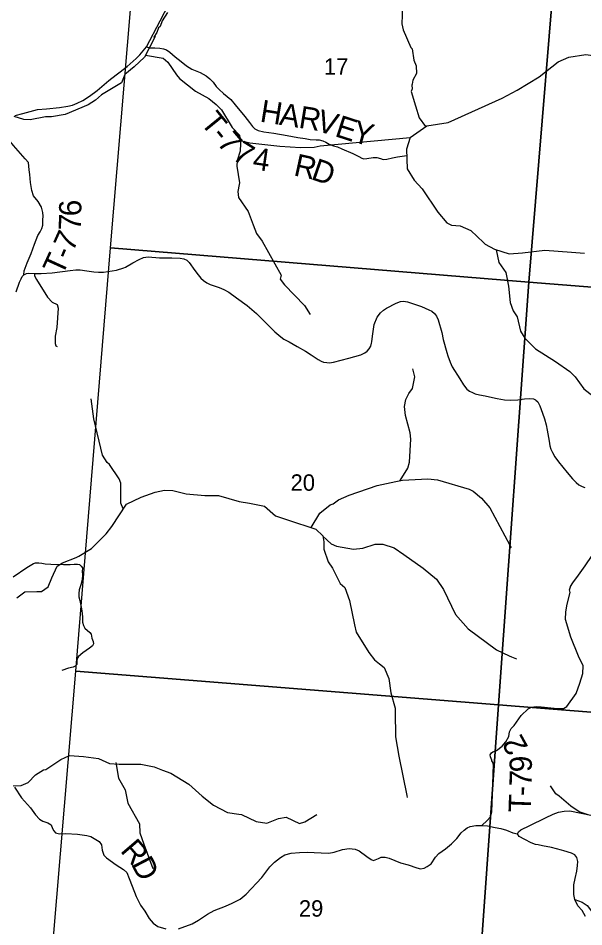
# Model space of a CAD drawing. Extents: x 1878108 to 2183446, y 146837 to 508383.
# Drawn here: x 1982625 to 1990241, y 255922 to 268162 of the extents above; entities that cross this region are included whole.
import ezdxf

# ---------------------------------------------------------------- set-up
doc = ezdxf.new("R2010")
doc.units = 0
for name, color, linetype in [('GM_X_County_Road', 7, 'Continuous'), ('GM_X_Minor_River', 7, 'Continuous'), ('GM_X_Section', 7, 'Continuous'), ('GM_X_Section_Text', 7, 'Continuous'), ('GM_X_State_Route', 7, 'Continuous'), ('GM_X_Township_Road', 7, 'Continuous'), ('GM_X_Township_Road_Text', 7, 'Continuous'), ('GM_X_Township_ROW', 7, 'Continuous')]:
    doc.layers.add(name, color=color, linetype=linetype)

msp = doc.modelspace()

# ---------------------------------------------------------------- linework, layer by layer
at = {"layer": 'GM_X_County_Road'}
for points in [[(1984047, 264799), (1984072, 264807), (1984168, 264867), (1984254, 264912), (1984314, 264940), (1984375, 264946), (1984526, 264934), (1984696, 264933), (1984805, 264931), (1984856, 264920), (1984894, 264901), (1984926, 264873), (1985005, 264761), (1985047, 264703), (1985085, 264660), (1985120, 264628), (1985165, 264599), (1985209, 264575), (1985331, 264536), (1985395, 264509), (1985462, 264469), (1985566, 264394), (1985707, 264291), (1985832, 264185), (1985976, 264039), (1986082, 263935), (1986160, 263871), (1986203, 263838), (1986272, 263802), (1986382, 263741), (1986494, 263676), (1986572, 263628), (1986664, 263565), (1986703, 263543), (1986737, 263530), (1986780, 263522), (1986819, 263521), (1986872, 263527), (1987076, 263580), (1987241, 263627), (1987294, 263653), (1987324, 263678), (1987351, 263707), (1987375, 263745), (1987383, 263782)], [(1982599, 264474), (1982644, 264606), (1982664, 264653), (1982681, 264681), (1982702, 264703), (1982736, 264721), (1982768, 264728), (1982846, 264723), (1982936, 264724), (1983085, 264733), (1983326, 264764), (1983401, 264772), (1983462, 264770), (1983549, 264757), (1983642, 264743), (1983706, 264739), (1983773, 264741), (1983947, 264767), (1984047, 264799)], [(1987383, 263782), (1987388, 263801), (1987397, 263877), (1987418, 264035), (1987460, 264133), (1987506, 264191), (1987545, 264227), (1987585, 264255), (1987716, 264324), (1987775, 264345), (1987815, 264349), (1987867, 264341), (1987950, 264316), (1988055, 264276), (1988156, 264231), (1988194, 264213), (1988230, 264182), (1988259, 264146), (1988281, 264099), (1988331, 263926), (1988349, 263835), (1988395, 263660), (1988410, 263613), (1988442, 263528), (1988471, 263465), (1988574, 263302), (1988620, 263225), (1988667, 263166), (1988703, 263137), (1988741, 263119), (1988780, 263103), (1988838, 263090), (1988912, 263073), (1988973, 263060), (1989073, 263037), (1989173, 263019), (1989254, 263015), (1989353, 263020), (1989444, 263036), (1989516, 263039), (1989562, 263035), (1989592, 263020), (1989597, 263015)], [(1989597, 263015), (1989623, 262994), (1989647, 262941), (1989686, 262839), (1989710, 262765), (1989734, 262682), (1989747, 262613), (1989774, 262463), (1989784, 262399), (1989798, 262355), (1989819, 262310), (1989852, 262251), (1989900, 262184), (1990015, 262042), (1990090, 261958), (1990140, 261907), (1990175, 261878), (1990219, 261854), (1990256, 261840)], [(1989625, 257025), (1989593, 257031), (1989533, 257052), (1989447, 257098), (1989372, 257139), (1989348, 257175), (1989361, 257202), (1989393, 257227), (1989515, 257286), (1989725, 257389), (1989827, 257441), (1989900, 257466), (1989977, 257481), (1990055, 257483), (1990360, 257420)], [(1989940, 256953), (1989808, 256989), (1989683, 257014), (1989625, 257025)], [(1990266, 256062), (1990217, 256140), (1990161, 256205), (1990120, 256291), (1990109, 256357), (1990105, 256421), (1990106, 256489), (1990125, 256574), (1990147, 256672), (1990158, 256750), (1990161, 256802), (1990147, 256854), (1990120, 256891), (1990075, 256916), (1989974, 256944), (1989940, 256953)]]:
    msp.add_lwpolyline(points, dxfattribs=at)
at = {"layer": 'GM_X_Minor_River'}
for points in [[(1987799, 268320), (1987792, 268084), (1987807, 268005), (1987913, 267769), (1987928, 267750), (1987954, 267595), (1987985, 267522), (1987987, 267417), (1987937, 267325), (1987931, 267272), (1987924, 267258), (1987930, 267208), (1987915, 267174), (1987973, 266980), (1988023, 266819), (1988110, 266702)], [(1984636, 268239), (1984564, 268126), (1984539, 268051), (1984514, 268034), (1984493, 267971), (1984453, 267905)], [(1984453, 267905), (1984469, 267917), (1984325, 267637), (1984186, 267508), (1984062, 267404), (1984016, 267290), (1983748, 267130), (1983667, 267057), (1983568, 266993), (1983256, 266866), (1983075, 266832), (1982991, 266833), (1982785, 266793), (1982703, 266799), (1982571, 266838)], [(1984341, 267665), (1984577, 267622), (1984642, 267570), (1984759, 267399), (1984798, 267350), (1985011, 267177), (1985191, 267080), (1985290, 267001), (1985363, 266927), (1985506, 266690), (1985607, 266585), (1985619, 266474), (1985614, 266369), (1985576, 266243), (1985570, 266167), (1985605, 265946), (1985602, 265922), (1985581, 265825), (1985594, 265747), (1985720, 265558), (1985791, 265376), (1985832, 265263), (1985909, 265159), (1986167, 264699), (1986155, 264647), (1986210, 264569), (1986481, 264291), (1986555, 264170)], [(1987901, 266556), (1988127, 266713), (1988413, 266756), (1989140, 267085), (1989346, 267190), (1989642, 267373), (1989897, 267572), (1990040, 267635), (1990269, 267672), (1990428, 267649), (1990556, 267606), (1990778, 267478), (1990917, 267300), (1991011, 267209), (1991051, 267178), (1991140, 267136), (1991342, 267084)], [(1985615, 266512), (1985743, 266481), (1986147, 266438), (1986425, 266419), (1986612, 266424), (1986692, 266441), (1987901, 266556), (1987856, 266396), (1987864, 266134), (1987956, 265981), (1988064, 265863), (1988276, 265547), (1988399, 265404), (1988461, 265375), (1988577, 265366), (1988719, 265300), (1988889, 265141), (1988915, 265119), (1989039, 265051), (1989236, 264989), (1989416, 265001), (1989717, 265035), (1990075, 265008), (1990249, 264996)], [(1989062, 265043), (1989099, 264873), (1989193, 264738), (1989228, 264551), (1989251, 264334), (1989292, 264221), (1989344, 264137), (1989389, 263945), (1989447, 263850), (1989592, 263708), (1989860, 263535), (1990053, 263401), (1990125, 263330), (1990240, 263171), (1990363, 263076), (1990388, 263060), (1990756, 262665)], [(1987767, 261932), (1987871, 262099), (1987893, 262180), (1987914, 262493), (1987904, 262578), (1987842, 262811), (1987826, 262931), (1987846, 263024), (1987886, 263104), (1987935, 263175), (1987964, 263332), (1987939, 263440)], [(1984040, 261552), (1984009, 261630), (1984009, 261898), (1983987, 261955), (1983855, 262149), (1983823, 262178), (1983762, 262276), (1983646, 262765), (1983608, 263033)], [(1986571, 261299), (1986687, 261492), (1986825, 261605), (1986866, 261619), (1986940, 261676), (1987083, 261737), (1987460, 261868), (1987712, 261921), (1987800, 261939), (1988143, 261958), (1988270, 261941), (1988699, 261816), (1988752, 261790), (1988864, 261696), (1988978, 261564), (1989243, 261065), (1989263, 261033)], [(1984082, 261616), (1984283, 261710), (1984471, 261778), (1984595, 261803), (1984707, 261800), (1984887, 261753), (1985139, 261734), (1985323, 261730), (1985599, 261653), (1985740, 261631), (1985940, 261589), (1986092, 261460), (1986251, 261403), (1986634, 261278), (1986726, 261190), (1986743, 261106), (1986741, 261076), (1986740, 261008), (1986799, 260837), (1986859, 260754), (1986960, 260546), (1987024, 260492), (1987086, 260317), (1987154, 259990), (1987176, 259890), (1987346, 259617), (1987422, 259519), (1987492, 259466), (1987555, 259414), (1987615, 259265), (1987642, 259072), (1987700, 258867), (1987701, 258817), (1987706, 258482), (1987749, 258222), (1987857, 257692), (1987863, 257663)], [(1982607, 260354), (1982716, 260436), (1982876, 260441), (1982938, 260439), (1983029, 260503), (1983080, 260621), (1983148, 260778), (1983224, 260827), (1983407, 260898), (1983442, 260913), (1983614, 261016), (1983810, 261218), (1983884, 261315), (1984082, 261616)], [(1986728, 261184), (1986841, 261081), (1986910, 261051), (1987138, 261011), (1987265, 261024), (1987434, 261077), (1987534, 261076), (1987687, 261026), (1987820, 260936), (1988080, 260754), (1988257, 260603), (1988350, 260468), (1988514, 260127), (1988685, 259936), (1989066, 259653), (1989235, 259573), (1989266, 259561), (1989333, 259534)], [(1982559, 257821), (1982664, 257824), (1982759, 257868), (1982860, 257968), (1982967, 258035), (1982996, 258043), (1983198, 258174), (1983314, 258228), (1983506, 258215), (1983707, 258188), (1983857, 258121), (1983985, 258114), (1984276, 258115), (1984458, 258076), (1984570, 258032), (1984680, 257991), (1984925, 257845), (1985103, 257684), (1985257, 257561), (1985443, 257464), (1985598, 257439), (1985630, 257433), (1985830, 257341), (1985975, 257317), (1986132, 257379), (1986234, 257400), (1986411, 257314), (1986483, 257335), (1986646, 257436)], [(1983938, 258136), (1983974, 257924), (1984066, 257767), (1984100, 257588), (1984260, 257311), (1984265, 257188), (1984317, 257036), (1984437, 256708)], [(1990302, 257429), (1990178, 257470), (1990065, 257546), (1989911, 257681), (1989863, 257714), (1989792, 257820)]]:
    msp.add_lwpolyline(points, dxfattribs=at)
at = {"layer": 'GM_X_Section'}
for points in [[(1989956, 270098), (1989500, 264608), (1983869, 265068), (1984327, 270526)], [(1995164, 269702), (1994764, 264190), (1989500, 264608), (1989956, 270098)], [(1983869, 265068), (1989500, 264608), (1989093, 258913), (1983403, 259365)], [(1989500, 264608), (1994764, 264190), (1994358, 258494), (1989093, 258913)], [(1983403, 259365), (1989093, 258913), (1988704, 253421), (1982941, 253857)], [(1989093, 258913), (1994358, 258494), (1993994, 253007), (1988704, 253421)]]:
    msp.add_lwpolyline(points, close=True, dxfattribs=at)
at = {"layer": 'GM_X_State_Route'}
msp.add_lwpolyline([(1982585, 266851), (1982687, 266879), (1982788, 266907), (1982887, 266930), (1983006, 266943), (1983181, 266959), (1983296, 266976), (1983358, 266989), (1983419, 267015), (1983495, 267052), (1983586, 267112), (1983688, 267188), (1983848, 267321), (1983943, 267397), (1984092, 267510), (1984212, 267618), (1984265, 267670), (1984309, 267722), (1984351, 267774), (1984536, 268125), (1984706, 268457)], dxfattribs=at)
at = {"layer": 'GM_X_Township_Road'}
for points in [[(1984351, 267774), (1984395, 267761), (1984464, 267762), (1984531, 267758), (1984583, 267749), (1984623, 267734), (1984665, 267703), (1984739, 267640), (1984818, 267579), (1984893, 267521), (1984964, 267477), (1985075, 267429), (1985157, 267387), (1985206, 267347), (1985249, 267301), (1985292, 267243), (1985331, 267199), (1985391, 267149), (1985489, 267065), (1985549, 266996), (1985679, 266837), (1985742, 266756), (1985780, 266701), (1985812, 266671), (1985855, 266649), (1985934, 266633), (1986068, 266611), (1986245, 266582), (1986391, 266554), (1986489, 266539), (1986558, 266528), (1986637, 266525), (1986676, 266521), (1986726, 266510), (1986766, 266491), (1986813, 266463), (1986870, 266443), (1986925, 266427), (1986982, 266404), (1987130, 266341), (1987211, 266300), (1987252, 266277), (1987280, 266267), (1987319, 266270), (1987407, 266284), (1987456, 266285), (1987506, 266270), (1987539, 266259), (1987590, 266262), (1987664, 266280), (1987733, 266295), (1987859, 266311)], [(1982702, 264703), (1982706, 264759), (1982746, 264865), (1982798, 264994), (1982845, 265119), (1982891, 265235), (1982920, 265283), (1982943, 265329), (1982955, 265373), (1982957, 265433), (1982958, 265445)], [(1982846, 264723), (1982846, 264691), (1982870, 264644), (1983020, 264406), (1983083, 264336), (1983151, 264305), (1983162, 264257), (1983144, 263996), (1983121, 263877), (1983123, 263812), (1983122, 263781), (1983132, 263749), (1983150, 263740)], [(1990063, 260504), (1990063, 260505), (1990095, 260556), (1990169, 260657), (1990261, 260785), (1990354, 260925), (1990422, 261041), (1990435, 261086), (1990439, 261140), (1990439, 261191), (1990421, 261373), (1990415, 261541), (1990410, 261651), (1990422, 261694), (1990444, 261735), (1990479, 261767), (1990607, 261839), (1990696, 261868)], [(1982556, 260638), (1982743, 260764), (1982830, 260817), (1982860, 260825), (1982903, 260826), (1982945, 260820), (1982988, 260810), (1983067, 260807), (1983234, 260802), (1983324, 260802), (1983379, 260808)], [(1983379, 260808), (1983382, 260808), (1983423, 260808), (1983451, 260801), (1983474, 260782), (1983490, 260759), (1983488, 260706), (1983490, 260666), (1983488, 260597), (1983470, 260530), (1983445, 260460), (1983440, 260413), (1983442, 260368), (1983456, 260318), (1983476, 260206), (1983488, 260141), (1983491, 260095), (1983492, 260026), (1983503, 259983), (1983521, 259947), (1983590, 259885), (1983608, 259862), (1983619, 259812), (1983633, 259766), (1983639, 259733), (1983628, 259706), (1983586, 259677), (1983495, 259614), (1983437, 259565), (1983419, 259538), (1983414, 259501), (1983413, 259458), (1983394, 259433), (1983364, 259419), (1983302, 259406), (1983214, 259377)], [(1988869, 257289), (1988942, 257352), (1988987, 257405), (1989003, 257472), (1989015, 257821), (1989023, 258001), (1989026, 258090), (1989023, 258131), (1989004, 258160)], [(1982576, 257801), (1982671, 257661), (1982792, 257524), (1982857, 257431), (1982912, 257371), (1982957, 257346), (1983026, 257322), (1983068, 257296), (1983086, 257248), (1983104, 257215), (1983127, 257187), (1983183, 257174), (1983269, 257180), (1983426, 257170), (1983549, 257154), (1983605, 257140), (1983716, 257070), (1983748, 257027), (1983756, 256954), (1983779, 256885), (1983813, 256852), (1983946, 256757), (1984045, 256693), (1984086, 256652), (1984118, 256575), (1984192, 256389), (1984216, 256329), (1984274, 256212), (1984330, 256131), (1984391, 256036), (1984443, 255969), (1984506, 255928), (1984612, 255893)], [(1984783, 255896), (1984969, 255962), (1985051, 256012), (1985173, 256094), (1985265, 256141), (1985418, 256202), (1985508, 256241), (1985616, 256296), (1985697, 256362), (1985905, 256588), (1986015, 256732), (1986077, 256792), (1986156, 256857), (1986217, 256892), (1986300, 256912), (1986413, 256921), (1986515, 256926), (1986703, 256917), (1986807, 256914), (1986882, 256928), (1986994, 256964), (1987083, 256978), (1987161, 256969), (1987216, 256945), (1987318, 256870), (1987378, 256827), (1987410, 256817), (1987477, 256842), (1987513, 256859), (1987565, 256861), (1987619, 256849), (1987773, 256785), (1987877, 256757), (1987994, 256718), (1988043, 256705), (1988090, 256710), (1988134, 256733), (1988185, 256772), (1988245, 256861), (1988287, 256911), (1988378, 256973), (1988460, 257041), (1988531, 257112), (1988591, 257186), (1988631, 257222), (1988672, 257256), (1988710, 257272), (1988786, 257288), (1988869, 257289), (1988945, 257281), (1989048, 257261), (1989126, 257246), (1989201, 257223), (1989285, 257186), (1989348, 257175)], [(1990120, 256291), (1990220, 256254), (1990288, 256210), (1990345, 256132), (1990456, 256054), (1990612, 256043), (1990733, 256047), (1991000, 256018), (1991195, 255980), (1991421, 255969), (1991598, 255960), (1991709, 255964), (1991772, 255977), (1991773, 256051)]]:
    msp.add_lwpolyline(points, dxfattribs=at)
at = {"layer": 'GM_X_Township_ROW'}
for points in [[(1982958, 265445), (1982961, 265496), (1982957, 265546), (1982937, 265617), (1982893, 265692), (1982831, 265767), (1982808, 265840), (1982793, 265949), (1982784, 266058), (1982775, 266118), (1982762, 266219), (1982719, 266266), (1982560, 266447), (1982292, 266764)], [(1989004, 258160), (1989001, 258165), (1988984, 258210), (1988982, 258237), (1988998, 258267), (1989016, 258277), (1989064, 258295), (1989143, 258356), (1989192, 258412), (1989230, 258486), (1989239, 258550), (1989261, 258595), (1989305, 258635), (1989398, 258768), (1989493, 258860), (1989539, 258880), (1989601, 258889), (1989667, 258885), (1989796, 258871), (1989892, 258861), (1989967, 258863), (1990014, 258890), (1990140, 259064), (1990188, 259202), (1990226, 259334), (1990232, 259437), (1990170, 259567), (1990066, 259824), (1989997, 260064), (1989999, 260165), (1990019, 260267), (1990059, 260424), (1990049, 260461), (1990063, 260504)]]:
    msp.add_lwpolyline(points, dxfattribs=at)

# ---------------------------------------------------------------- texts
at = {"layer": 'GM_X_Section_Text'}
for s, p in [('17', (1986742, 267400)), ('20', (1986293, 261796)), ('29', (1986405, 256059))]:
    msp.add_text(s, height=221, rotation=0, dxfattribs=at).set_placement(p)
at = {"layer": 'GM_X_Township_Road_Text'}
for s, rotation, p in [('H', 350.8856, (1985870, 266770)), ('A', 350.8853, (1986130, 266728)), ('R', 350.7706, (1986391, 266687)), ('T', 309.1578, (1985069, 266752)), ('V', 343.7721, (1986625, 266649)), ('E', 342.0353, (1986876, 266576)), ('Y', 344.9705, (1987105, 266502)), ('-', 309.2842, (1985211, 266577)), ('7', 310.1316, (1985292, 266478)), ('7', 328.8041, (1985492, 266268)), ('4', 351.7787, (1985772, 266128)), ('R', 347.7972, (1986323, 266046)), ('D', 340.9199, (1986555, 265997)), ('6', 89.9245, (1983476, 265493)), ('7', 87.3682, (1983467, 265294)), ('7', 65.6161, (1983362, 265005)), ('T', 65.5073, (1983218, 264680)), ('-', 67.274, (1983316, 264894)), ('2', 118.8986, (1989499, 258343)), ('9', 91.0669, (1989544, 258007)), ('7', 88.396, (1989538, 257807)), ('-', 88.0444, (1989534, 257681)), ('T', 87.9618, (1989526, 257457)), ('R', 310.6934, (1983990, 256942)), ('D', 297.5466, (1984140, 256770))]:
    msp.add_text(s, height=300, rotation=rotation, dxfattribs=at).set_placement(p)

doc.saveas('drawing.dxf')
